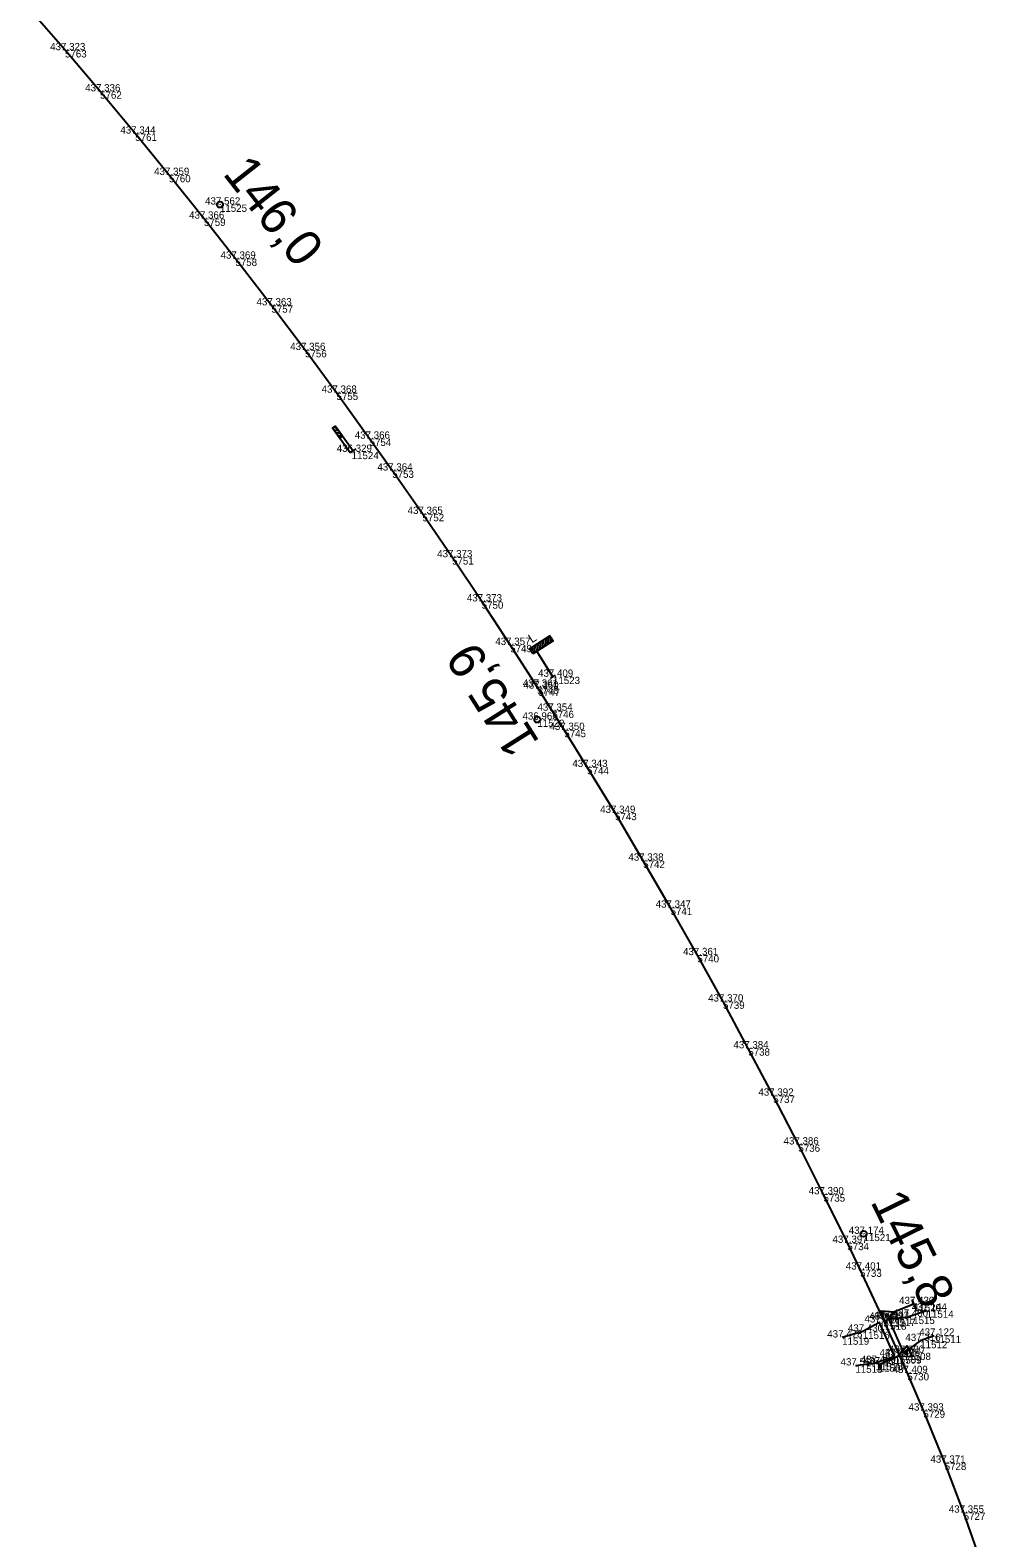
# Model space of a CAD drawing. Extents: x -654154 to -652650, y -1166925 to -1164904.
# Drawn here: x -652836.8 to -652679.3, y -1166415.2 to -1166166.6 of the extents above; entities that cross this region are included whole.
import ezdxf

# ---------------------------------------------------------------- set-up
doc = ezdxf.new("R2010")
doc.units = 0
for name, color, linetype in [('Vrstva 1', 7, 'Continuous'), ('Vrstva 4', 7, 'Continuous'), ('Vrstva 51', 7, 'Continuous'), ('Vrstva 6', 7, 'Continuous'), ('Vrstva 60', 7, 'Continuous'), ('Vrstva 61', 7, 'Continuous'), ('Vrstva 7', 7, 'Continuous')]:
    doc.layers.add(name, color=color, linetype=linetype)

msp = doc.modelspace()

# ---------------------------------------------------------------- linework, layer by layer
at = {"layer": 'Vrstva 1'}
msp.add_lwpolyline([(-652679.83, -1166419.36), (-652682.76, -1166411.06), (-652685.9, -1166402.83), (-652689.41, -1166394.22), (-652692.05, -1166388.04), (-652693.3, -1166385.2), (-652695.99, -1166379.22), (-652699.85, -1166370.98), (-652701.96, -1166366.58), (-652705.89, -1166358.58), (-652710.03, -1166350.36), (-652714.18, -1166342.31), (-652718.3, -1166334.51), (-652722.47, -1166326.79), (-652726.7, -1166319.14), (-652731.12, -1166311.32), (-652735.63, -1166303.57), (-652740.28, -1166295.69), (-652744.87, -1166288.13), (-652748.65, -1166282.01), (-652750.63, -1166278.85), (-652752.94, -1166275.2), (-652753.14, -1166274.89), (-652757.57, -1166268), (-652762.28, -1166260.83), (-652767.17, -1166253.55), (-652772.05, -1166246.41), (-652777.04, -1166239.25), (-652780.77, -1166234), (-652786.24, -1166226.42), (-652791.42, -1166219.38), (-652796.97, -1166212.02), (-652802.91, -1166204.32), (-652808.1, -1166197.72), (-652813.87, -1166190.52), (-652819.44, -1166183.7), (-652825.23, -1166176.74), (-652831.02, -1166169.95), (-652836.78, -1166163.34)], dxfattribs=at)
at = {"layer": 'Vrstva 4'}
for p, q in [((-652690.68, -1166377.38), (-652691.26, -1166375.93)), ((-652695.22, -1166378.6), (-652695.67, -1166378.41)), ((-652697.09, -1166385.9), (-652696.47, -1166387.33)), ((-652692.57, -1166384.58), (-652692.12, -1166384.76))]:
    msp.add_line(p, q, dxfattribs=at)
for points in [[(-652690.97, -1166376.66), (-652694.19, -1166377.96), (-652695.68, -1166379.63), (-652696.44, -1166377.78), (-652694.19, -1166377.96)], [(-652696.78, -1166386.62), (-652693.59, -1166385.24), (-652692.14, -1166383.54), (-652691.34, -1166385.37), (-652693.59, -1166385.24)]]:
    msp.add_lwpolyline(points, dxfattribs=at)
for centre in [(-652695.44, -1166378.5), (-652692.35, -1166384.67)]:
    msp.add_circle(centre, 0.248, dxfattribs=at)
at = {"layer": 'Vrstva 51'}
for points in [[(-652687.65, -1166381.88), (-652689.93, -1166382.75), (-652692.64, -1166384.7), (-652695.14, -1166379.1), (-652691.99, -1166378.75), (-652688.88, -1166377.73)], [(-652700.63, -1166386.79), (-652697.3, -1166386.38), (-652694.18, -1166385.28), (-652696.67, -1166379.7), (-652699.42, -1166381.21), (-652702.82, -1166382.18)]]:
    msp.add_lwpolyline(points, dxfattribs=at)
at = {"layer": 'Vrstva 6'}
for p, q in [((-652786.12, -1166232.29), (-652786.76, -1166232.18)), ((-652785.81, -1166232.72), (-652786.64, -1166232.58)), ((-652785.5, -1166233.16), (-652786.34, -1166233.01)), ((-652785.27, -1166233.58), (-652786.03, -1166233.45)), ((-652785.7, -1166233.88), (-652785.72, -1166233.88)), ((-652783.49, -1166235.99), (-652783, -1166235.65)), ((-652751.61, -1166266.86), (-652751.92, -1166268.24)), ((-652751.16, -1166266.57), (-652751.47, -1166267.95)), ((-652750.82, -1166266.79), (-652751.03, -1166267.67)), ((-652753.85, -1166268.28), (-652754.05, -1166269.17)), ((-652753.4, -1166267.99), (-652753.71, -1166269.37)), ((-652752.95, -1166267.71), (-652753.26, -1166269.09)), ((-652750.52, -1166273.25), (-652753.19, -1166269.04)), ((-652752.51, -1166267.43), (-652752.82, -1166268.8)), ((-652752.06, -1166267.14), (-652752.37, -1166268.52)), ((-652750.95, -1166273.51), (-652750.1, -1166272.98))]:
    msp.add_line(p, q, dxfattribs=at)
for points in [[(-652786.38, -1166231.92), (-652785.23, -1166233.55), (-652785.71, -1166233.89), (-652786.87, -1166232.26)], [(-652753.86, -1166269.47), (-652754.4, -1166268.62), (-652751.02, -1166266.48), (-652750.48, -1166267.33)]]:
    msp.add_lwpolyline(points, close=True, dxfattribs=at)
msp.add_lwpolyline([(-652783.98, -1166236.34), (-652786.87, -1166232.26), (-652786.38, -1166231.92), (-652783.49, -1166235.99), (-652783.98, -1166236.34)], dxfattribs=at)
at = {"layer": 'Vrstva 60'}
for p, q in [((-652831.02, -1166169.95), (-652831.02, -1166169.95)), ((-652825.23, -1166176.74), (-652825.23, -1166176.74)), ((-652819.44, -1166183.7), (-652819.44, -1166183.7)), ((-652813.87, -1166190.52), (-652813.87, -1166190.52)), ((-652805.46, -1166195.4), (-652805.46, -1166195.4)), ((-652808.1, -1166197.72), (-652808.1, -1166197.72)), ((-652802.91, -1166204.32), (-652802.91, -1166204.32)), ((-652796.97, -1166212.02), (-652796.97, -1166212.02)), ((-652791.42, -1166219.38), (-652791.42, -1166219.38)), ((-652786.24, -1166226.42), (-652786.24, -1166226.42)), ((-652780.77, -1166234), (-652780.77, -1166234)), ((-652783.73, -1166236.17), (-652783.73, -1166236.17)), ((-652777.04, -1166239.25), (-652777.04, -1166239.25)), ((-652772.05, -1166246.41), (-652772.05, -1166246.41)), ((-652767.17, -1166253.55), (-652767.17, -1166253.55)), ((-652762.28, -1166260.83), (-652762.28, -1166260.83)), ((-652757.57, -1166268), (-652757.57, -1166268)), ((-652750.52, -1166273.25), (-652750.52, -1166273.25)), ((-652753.14, -1166274.89), (-652753.14, -1166274.89)), ((-652752.94, -1166275.2), (-652752.94, -1166275.2)), ((-652750.63, -1166278.85), (-652750.63, -1166278.85)), ((-652753.09, -1166280.31), (-652753.09, -1166280.31)), ((-652748.65, -1166282.01), (-652748.65, -1166282.01)), ((-652744.87, -1166288.13), (-652744.87, -1166288.13)), ((-652740.28, -1166295.69), (-652740.28, -1166295.69)), ((-652735.63, -1166303.57), (-652735.63, -1166303.57)), ((-652731.12, -1166311.32), (-652731.12, -1166311.32)), ((-652726.7, -1166319.14), (-652726.7, -1166319.14)), ((-652722.47, -1166326.79), (-652722.47, -1166326.79)), ((-652718.3, -1166334.51), (-652718.3, -1166334.51)), ((-652714.18, -1166342.31), (-652714.18, -1166342.31)), ((-652710.03, -1166350.36), (-652710.03, -1166350.36)), ((-652705.89, -1166358.58), (-652705.89, -1166358.58)), ((-652699.28, -1166365.09), (-652699.28, -1166365.09)), ((-652701.96, -1166366.58), (-652701.96, -1166366.58)), ((-652699.85, -1166370.98), (-652699.85, -1166370.98)), ((-652691.99, -1166378.75), (-652691.99, -1166378.75)), ((-652690.97, -1166376.66), (-652690.97, -1166376.66)), ((-652688.88, -1166377.73), (-652688.88, -1166377.73)), ((-652699.42, -1166381.21), (-652699.42, -1166381.21)), ((-652696.67, -1166379.7), (-652696.67, -1166379.7)), ((-652695.99, -1166379.22), (-652695.99, -1166379.22)), ((-652695.14, -1166379.1), (-652695.14, -1166379.1)), ((-652702.82, -1166382.18), (-652702.82, -1166382.18)), ((-652689.93, -1166382.75), (-652689.93, -1166382.75)), ((-652687.65, -1166381.88), (-652687.65, -1166381.88)), ((-652694.18, -1166385.28), (-652694.18, -1166385.28)), ((-652693.3, -1166385.2), (-652693.3, -1166385.2)), ((-652692.64, -1166384.7), (-652692.64, -1166384.7)), ((-652700.63, -1166386.79), (-652700.63, -1166386.79)), ((-652697.3, -1166386.38), (-652697.3, -1166386.38)), ((-652696.78, -1166386.62), (-652696.78, -1166386.62)), ((-652692.05, -1166388.04), (-652692.05, -1166388.04)), ((-652689.41, -1166394.22), (-652689.41, -1166394.22)), ((-652685.9, -1166402.83), (-652685.9, -1166402.83)), ((-652682.76, -1166411.06), (-652682.76, -1166411.06))]:
    msp.add_line(p, q, dxfattribs=at)
at = {"layer": 'Vrstva 7'}
for p, q in [((-652805.49, -1166195.36), (-652805.43, -1166195.44)), ((-652753.06, -1166280.35), (-652753.12, -1166280.27)), ((-652699.31, -1166365.05), (-652699.26, -1166365.14))]:
    msp.add_line(p, q, dxfattribs=at)
for centre in [(-652805.46, -1166195.4), (-652753.09, -1166280.31), (-652699.28, -1166365.09)]:
    msp.add_circle(centre, 0.5, dxfattribs=at)

# ---------------------------------------------------------------- texts
at = {"layer": 'Vrstva 6'}
msp.add_text('L', height=1.5, rotation=32.3317, dxfattribs=at).set_placement((-652754, -1166267.75))
at = {"layer": 'Vrstva 60'}
for s, p in [('5763', (-652831.02, -1166171.15)), ('5762', (-652825.23, -1166177.94)), ('5761', (-652819.44, -1166184.9)), ('5760', (-652813.87, -1166191.72)), ('11525', (-652805.46, -1166196.6)), ('5759', (-652808.1, -1166198.92)), ('5758', (-652802.91, -1166205.52)), ('5757', (-652796.97, -1166213.22)), ('5756', (-652791.42, -1166220.58)), ('5755', (-652786.24, -1166227.62)), ('5754', (-652780.77, -1166235.2)), ('11524', (-652783.73, -1166237.37)), ('5753', (-652777.04, -1166240.45)), ('5752', (-652772.05, -1166247.61)), ('5751', (-652767.17, -1166254.75)), ('5750', (-652762.28, -1166262.03)), ('5749', (-652757.57, -1166269.2)), ('11523', (-652750.52, -1166274.45)), ('5748', (-652753.14, -1166276.09)), ('5747', (-652752.94, -1166276.4)), ('5746', (-652750.63, -1166280.05)), ('11522', (-652753.09, -1166281.51)), ('5745', (-652748.65, -1166283.21)), ('5744', (-652744.87, -1166289.33)), ('5743', (-652740.28, -1166296.89)), ('5742', (-652735.63, -1166304.77)), ('5741', (-652731.12, -1166312.52)), ('5740', (-652726.7, -1166320.34)), ('5739', (-652722.47, -1166327.99)), ('5738', (-652718.3, -1166335.71)), ('5737', (-652714.18, -1166343.51)), ('5736', (-652710.03, -1166351.56)), ('5735', (-652705.89, -1166359.78)), ('11521', (-652699.28, -1166366.29)), ('5734', (-652701.96, -1166367.78)), ('5733', (-652699.85, -1166372.18)), ('11515', (-652691.99, -1166379.95)), ('11520', (-652690.97, -1166377.85)), ('11514', (-652688.88, -1166378.93)), ('11516', (-652699.42, -1166382.41)), ('11518', (-652696.67, -1166380.9)), ('5732', (-652695.99, -1166380.42)), ('11517', (-652695.14, -1166380.3)), ('11519', (-652702.82, -1166383.38)), ('11512', (-652689.93, -1166383.95)), ('11511', (-652687.65, -1166383.08)), ('11509', (-652694.18, -1166386.49)), ('5731', (-652693.3, -1166386.4)), ('11508', (-652692.64, -1166385.9)), ('11513', (-652700.63, -1166387.99)), ('11510', (-652697.3, -1166387.58)), ('11507', (-652696.78, -1166387.82)), ('5730', (-652692.05, -1166389.24)), ('5729', (-652689.41, -1166395.42)), ('5728', (-652685.9, -1166404.03)), ('5727', (-652682.76, -1166412.26))]:
    msp.add_text(s, height=1.2, dxfattribs=at).set_placement(p)
at = {"layer": 'Vrstva 61'}
for s, p in [('437.323', (-652833.47, -1166169.95)), ('437.336', (-652827.69, -1166176.74)), ('437.344', (-652821.89, -1166183.7)), ('437.359', (-652816.32, -1166190.52)), ('437.562', (-652807.91, -1166195.4)), ('437.366', (-652810.55, -1166197.72)), ('437.369', (-652805.36, -1166204.32)), ('437.363', (-652799.42, -1166212.02)), ('437.356', (-652793.87, -1166219.38)), ('437.368', (-652788.69, -1166226.42)), ('437.366', (-652783.22, -1166234)), ('436.329', (-652786.19, -1166236.17)), ('437.364', (-652779.49, -1166239.25)), ('437.365', (-652774.5, -1166246.41)), ('437.373', (-652769.62, -1166253.55)), ('437.373', (-652764.73, -1166260.83)), ('437.357', (-652760.03, -1166268)), ('437.361', (-652755.5, -1166274.89)), ('437.360', (-652755.39, -1166275.2)), ('437.409', (-652752.98, -1166273.25)), ('436.965', (-652755.55, -1166280.31)), ('437.354', (-652753.08, -1166278.85)), ('437.350', (-652751.1, -1166282.01)), ('437.343', (-652747.32, -1166288.13)), ('437.349', (-652742.73, -1166295.69)), ('437.338', (-652738.08, -1166303.57)), ('437.347', (-652733.58, -1166311.32)), ('437.361', (-652729.06, -1166319.14)), ('437.370', (-652724.92, -1166326.79)), ('437.384', (-652720.75, -1166334.51)), ('437.392', (-652716.63, -1166342.31)), ('437.386', (-652712.48, -1166350.36)), ('437.390', (-652708.34, -1166358.58)), ('437.174', (-652701.73, -1166365.09)), ('437.397', (-652704.41, -1166366.58)), ('437.401', (-652702.21, -1166370.98)), ('437.430', (-652693.42, -1166376.66)), ('437.405', (-652699.13, -1166379.7)), ('437.421', (-652698.35, -1166379.22)), ('437.493', (-652697.59, -1166379.1)), ('437.400', (-652694.44, -1166378.75)), ('437.144', (-652691.33, -1166377.73)), ('437.478', (-652705.27, -1166382.18)), ('437.430', (-652701.87, -1166381.21)), ('437.122', (-652690.1, -1166381.88)), ('437.500', (-652695.09, -1166384.7)), ('437.316', (-652692.38, -1166382.75)), ('437.550', (-652703.08, -1166386.79)), ('437.489', (-652699.75, -1166386.38)), ('437.580', (-652699.23, -1166386.62)), ('437.416', (-652696.63, -1166385.28)), ('437.425', (-652695.75, -1166385.2)), ('437.409', (-652694.5, -1166388.04)), ('437.393', (-652691.86, -1166394.22)), ('437.371', (-652688.25, -1166402.83)), ('437.355', (-652685.22, -1166411.06))]:
    msp.add_text(s, height=1.2, dxfattribs=at).set_placement(p)
at = {"layer": 'Vrstva 7'}
for s, rotation, p in [('146,0', 308.1952, (-652805.13, -1166190.34)), ('145,9', 122.3317, (-652752.62, -1166284.02)), ('145,8', 296.137, (-652698.22, -1166359.76))]:
    msp.add_text(s, height=6, rotation=rotation, dxfattribs=at).set_placement(p)

doc.saveas('drawing.dxf')
